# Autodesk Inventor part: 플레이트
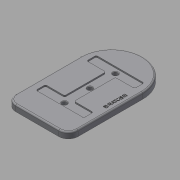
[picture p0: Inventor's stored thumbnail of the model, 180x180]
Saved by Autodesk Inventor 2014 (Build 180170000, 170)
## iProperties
Created: 2016-08
Part Number: 플레이트
Material: 알루미늄 6061
Document SubType Name: Modeling
Designer: mduedu
Density: 2.71 g/cm^3
Appearance: 기본값
Author: mduedu
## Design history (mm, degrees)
sketch "스케치1" dims "d0" = 220, "d2" = 130
  geometry: L1 (110, 65)-(-45, 65); L2 (-45, 65)-(-45, -65); L3 (-45, -65)-(110, -65); L4 (45, -65)-(45, 65); L5 (45, 65)-(-45, -65); L6 (-45, 65)-(45, -65); L7 (110, -65)-(110, 65); 5 further points
  constraints: 14 end point, 5 midpoint, 3 parallel, 2 point on line, 2 vertical alignment, 1 coincident, 1 horizontal, 1 perpendicular, 1 vertical, 4 other
extrude "돌출1" new body sketch "스케치1" distance "d3" = 13; taper "d4" = 0 deg
sketch "스케치2"
  geometry: L1 (-63, -50)-(63, -50); L2 (63, -50)-(63, 50); L3 (63, 50)-(-63, 50); L4 (-63, 50)-(-63, -50); L5 (-63, -50)-(63, 50); L6 (63, -50)-(-63, 50); L7 (-63, 50)-(-43, 50); L8 (-43, 50)-(-43, -50); L9 (-43, -50)-(-63, -50); L10 (-63, -50)-(-63, 50); L11 (63, 50)-(43, 50); L12 (43, 50)-(43, -50); L13 (43, -50)-(63, -50); L14 (63, -50)-(63, 50); L15 (-43, -10)-(43, -10); L16 (43, -10)-(43, 10); L17 (43, 10)-(-43, 10); L18 (-43, 10)-(-43, -10); L19 (-43, -10)-(43, 10); L20 (43, -10)-(-43, 10); 1 further point
  constraints: 40 end point, 8 parallel, 4 horizontal, 4 midpoint, 4 perpendicular, 3 point on line
  dimensions: "d18" = 126 distance of L3.end L2.end; "d19" = 100 distance of L2.end L1.end; "d20" = 20 distance of L8.end L9.end; "d21" = 20 distance of L12.end L13.end (= d20); "d22" = 20 distance of L15.end L16.end
extrude "돌출3" cut sketch "스케치2" distance "d23" = 3; taper "d24" = 0 deg
fillet "모깎기6" dims "d25" = 3
sketch "스케치4"
  geometry: L1 (-40, -10)-(40, -10) reference; L2 (43, -13)-(43, -47) reference; L3 (40, 10)-(-40, 10) reference; L4 (-43, 13)-(-43, 47) reference; L5 (45, -65)-(-110, -65) reference; L6 (-110, 65)-(45, 65) reference; L7 (-53, 40)-(-53, -40); L8 (53, 40)-(53, -40); L9 (-53, 0)-(53, 0); L10 (-46, 50)-(-60, 50) reference; L11 (-63, 47)-(-63, -47) reference; L12 (-60, -50)-(-46, -50) reference; L13 (-43, -47)-(-43, -13) reference; L14 (46, -50)-(60, -50) reference; L15 (63, -47)-(63, 47) reference; L16 (60, 50)-(46, 50) reference; L17 (43, 47)-(43, 13) reference; L18 (-110, -65)-(-110, 65) reference; C1 r 5 at (-53, 0); C2 r 5 at (0, 0); C3 r 5 at (53, 0); A1 r 3 centre (-40, -13) between (-40, -10) and (-43, -13) reference; A2 r 3 centre (40, -13) between (43, -13) and (40, -10) reference; A3 r 3 centre (40, 13) between (40, 10) and (43, 13) reference; A4 r 3 centre (-40, 13) between (-43, 13) and (-40, 10) reference; A5 r 65 centre (45, 0) between (45, -65) and (45, 65) reference; A6 r 3 centre (-46, 47) between (-43, 47) and (-46, 50) reference; A7 r 3 centre (-60, 47) between (-60, 50) and (-63, 47) reference; A8 r 3 centre (-60, -47) between (-63, -47) and (-60, -50) reference; A9 r 3 centre (-46, -47) between (-46, -50) and (-43, -47) reference; A10 r 3 centre (46, -47) between (43, -47) and (46, -50) reference; A11 r 3 centre (60, -47) between (60, -50) and (63, -47) reference; A12 r 3 centre (60, 47) between (63, 47) and (60, 50) reference; A13 r 3 centre (46, 47) between (46, 50) and (43, 47) reference; 1 further point
  constraints: 6 end point, 3 centre point, 3 coincident, 2 midpoint, 1 parallel, 1 perpendicular
  dimensions: "d26" = 10 diameter of C1; "d27" = 10 diameter of C2; "d28" = 10 diameter of C3
extrude "돌출4" cut sketch "스케치4" stored distance "d29" = 3; taper "d30" = 0 deg
chamfer "모따기2" distance "d31" = 1; stored, may be unused: second distance "d32" = 2, angle "d33" = 45 deg
fillet "모깎기7" dims "d34" = 20
fillet "모깎기1" dims "d14" = 3
sketch "스케치3"
  geometry: L1 (-90, -65)-(45, -65) reference; 3 further points
  constraints: 1 vertical alignment, 1 other
  dimensions: "d15" = 12 distance from line of point (0, -53) L1
feature "엠보싱1" sketch "스케치3" dims "d16" = 0.5, "d17" = 0
node "솔리드1"
node "절단 모서리 투영1"
